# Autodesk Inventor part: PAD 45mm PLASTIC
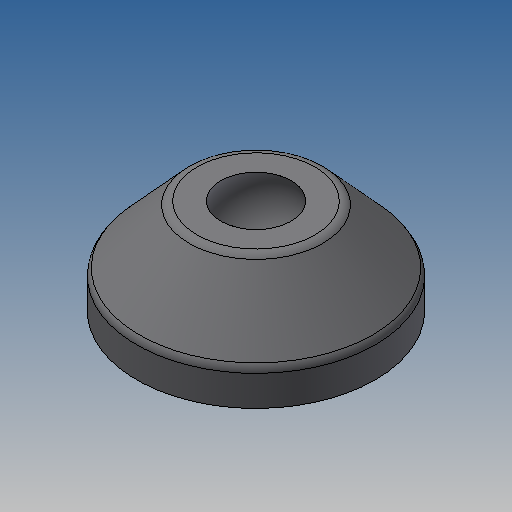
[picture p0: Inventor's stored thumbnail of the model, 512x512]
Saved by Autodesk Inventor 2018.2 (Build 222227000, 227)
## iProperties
Created: 2007-03
Part Number: PAD 45mm PLASTIC
Document SubType Name: Modeling
Designer: Andy Moles
Material: ABS Plastic
Mass: 16.1926 g
Surface Area: 57.8063 cm^2
Volume: 15.276 cm^3
Density: 1.06 g/cm^3
Appearance: Light Gray
Author: Andy Moles
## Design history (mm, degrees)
sketch "Sketch1"
  geometry: L1 (0, 0)-(22.5, 0); L2 (22.5, 0)-(22.5, 5.724); L3 (0, 0)-(0, 18); L4 (6.633, 18)-(11.118, 18); L5 (21.977, 7.073)-(12.595, 17.349); L6 (0, 0)-(0, 7); A1 r 7.5 centre (0, 14.5) between (0, 7) and (6.633, 18); A2 r 2 centre (11.118, 16) between (12.595, 17.349) and (11.118, 18); A3 r 2 centre (20.5, 5.724) between (22.5, 5.724) and (21.977, 7.073); 2 further points
  constraints: 12 end point, 6 point on circle, 6 point on line, 4 tangent, 3 centre point, 2 perpendicular, 1 collinear, 1 equal radius, 1 horizontal, 1 parallel
  dimensions: "d0" = 22.5 distance of L1.start L1.end; "d1" = 6.5 distance of L1.end point (22.5, 6.5); "d2" = 18 distance of L1.start L3.end; "d3" = 15 diameter of A1; "d4" = 3.5 distance of A1.centre L3.end; "d5" = 12 horizontal distance of point (12, 18) L1.start; "d6" = 2 radius of A2
revolve "Revolution1" sketch "Sketch1" stored, may be unused: angle "d7" = 90 deg
sketch "Sketch2"
  geometry: C1 r 22.5 at (0, 0) reference; C2 r 7.5 at (0, 0)
  constraints: 1 centre point, 1 coincident
  dimensions: "d8" = 15 diameter of C2
extrude "Extrusion1" cut sketch "Sketch2" distance "d9" = 1; taper "d10" = 0 deg
sketch "Sketch3"
  geometry: C1 r 7.5 at (0, 0) reference; C2 r 22.5 at (0, 0) reference; C3 r 18.5 at (0, 0)
  constraints: 1 centre point, 1 coincident
  dimensions: "d11" = 4 radial gap between concentric circles of C2 C3
extrude "Extrusion2" cut sketch "Sketch3" distance "d12" = 5; taper "d13" = 0 deg
body "Solid1"
